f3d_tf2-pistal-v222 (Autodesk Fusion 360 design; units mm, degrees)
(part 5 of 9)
sketch "Sketch81" plane through (0, 157.95, 0) normal (0, 1, 0) x axis (-1, 0, 0)
  line L1 (-8.4524, 10) -> (-5.806, 10)
  line L2 (-8.4524, 5.25) -> (-8.4524, 10)
  line L3 (-8.4524, 1) -> (-8.4524, 5.25)
  line L4 (8.4524, 1) -> (-8.4524, 1)
  line L5 (8.4524, 10) -> (8.4524, 1)
  line L6 (5.8059, 10) -> (8.4524, 10)
  line L7 (-8.4524, 13.0239) -> (-6.8669, 13.0239)
  line L8 (-8.4524, 10) -> (-5.806, 10)
  line L9 (-8.4524, 10) -> (-8.4524, 13.0239)
  arc A1 centre (0, 13.7351) radius 6.9036 clockwise from (5.8059, 10) to (-5.806, 10)
  arc A2 centre (0, 13.7351) radius 6.9036 clockwise from (5.8059, 10) to (-5.806, 10)
  arc A3 centre (0, 13.7351) radius 6.9036 clockwise from (-6.8669, 13.0239) to (6.8668, 13.0239)
  circle C1 centre (0, 13.7351) radius 6.9036
  point P10 (-5.806, 10)
  point P14 (-8.4524, 13.0239)
  point P19 (-8.4524, 13.0239)
  point P17 (-8.4524, 10)
  point P20 (-8.4524, 10)
  concentric A1 C1
  coincident P10 C1
  coincident P14 P19
  coincident P17 P20
extrude "Extrude77" new body sketch "Sketch81" profile of L1 L7 L8 C1 L9 against normal blind 2.1
mirror "Mirror24" mirrorStitchTolerance 0.1
combine "Combine75"
delete_face "DeleteFace79"
combine "Combine76" bodies "Barrel"
delete_face "DeleteFace80"
move_face "MoveFace115" TranslateX -0.232 TranslateY 0 TranslateZ 0
extrude "Extrude78" add of existing geometry blind 0
move_face "MoveFace116" TranslateX 0 TranslateY 0 TranslateZ 0
split "Split28" bodies "Trigger Pannel_R (1)"
remove_body "RemoveBody37"
move_face "MoveFace117" TranslateX 3 TranslateY 0 TranslateZ 0
split "Split29" bodies "Trigger Pannel_R (1)"
remove_body "RemoveBody38"
split "Split30" bodies "Trigger Pannel_L (1)"
remove_body "RemoveBody39"
move_face "MoveFace118" TranslateX -3 TranslateY 0 TranslateZ 0
split "Split31" bodies "Trigger Pannel_L (1)"
remove_body "RemoveBody40"
sketch "Sketch82" plane through (-0.0003, 0, 0) normal (-1, 0, 0) x axis (0, -1, 0)
  line L1 (-144.2618, -68.8977) -> (-159.3646, -64.9915)
  curve K1 (-143.2922, -67.2348) -> (-144.2618, -68.8977)
  curve K2 (-143.2922, -67.2348) -> (-146.2926, -63.0126)
  curve K3 (-146.2926, -63.0126) -> (-146.4498, -62.6853)
  curve K4 (-147.5496, -59.6077) -> (-148.3256, -54.5282)
  curve K5 (-146.4498, -62.6853) -> (-147.5496, -59.6077)
  curve K6 (-146.2926, -63.0126) -> (-146.4498, -62.6853)
  curve K7 (-134.7944, -30.1716) -> (-146.2926, -63.0126)
  curve K8 (-135.347, -29.366) -> (-134.7944, -30.1716)
  curve K9 (-136.1286, -29.6952) -> (-135.347, -29.366)
  line L2 (-136.7565, -29.9764) -> (-136.1286, -29.6952)
  line L3 (-136.8552, -29.6952) -> (-136.7565, -29.9764)
  line L4 (-144.3129, -29.6952) -> (-136.8552, -29.6952)
  line L5 (-159.3646, -64.9915) -> (-144.3129, -29.6952)
  line L6 (-145.5, -62.5) -> (-146.8762, -63.1863)
  line L7 (-147.4329, -53.781) -> (-145.5, -62.5)
  line L8 (-150, -53.781) -> (-147.4329, -53.781)
  line L9 (-146.8762, -63.1863) -> (-150, -53.781)
  horizontal L8
extrude "Extrude79" new body sketch "Sketch82" profile of L6 L7 L8 L9 against normal blind 8
move_face "MoveFace119" TranslateX 0 TranslateY 0 TranslateZ -0.3
fillet "Fillet95" radius 4
fillet "Fillet96" radius 1.5
mirror "Mirror25" mirrorStitchTolerance 0.1
combine "Combine77"
combine "Combine78"
move_face "MoveFace120" TranslateX 0 TranslateY 0 TranslateZ 0
move_face "MoveFace121" TranslateX 5 TranslateY 0 TranslateZ 0
split "Split32" bodies "GripAft_R (1)"
remove_body "RemoveBody41"
move_face "MoveFace122" TranslateX -5 TranslateY 0 TranslateZ 0
split "Split33" bodies "GripAft_L (1)"
remove_body "RemoveBody42"
sketch "Sketch83" plane through (-8.7048, 0, 0) normal (-1, 0, 0) x axis (0, -1, 0)
  line L1 (-245.977, -21.5753) -> (-249.4899, -14.9957)
  line L2 (-220.43, -21.5753) -> (-245.977, -21.5753)
  line L3 (-219.864, -18.4055) -> (-220.43, -21.5753)
  line L4 (-214.6554, -27.0757) -> (-215.9162, -18.4672)
  line L5 (-219.3284, -44.1367) -> (-214.6554, -27.0757)
  line L6 (-216.9388, -45.4009) -> (-218.364, -45.4009)
  line L7 (-215.7169, -43.7389) -> (-215.9754, -44.6687)
  line L8 (-216.8579, -41.6824) -> (-215.9084, -42.8355)
  line L9 (-208.8666, -10.9038) -> (-217.0504, -40.7825)
  line L10 (-248.3191, -10.9038) -> (-208.8666, -10.9038)
  line L11 (-249.4926, -13.1167) -> (-248.3191, -10.9038)
  line L12 (-213.391, -27.422) -> (-214.6554, -27.0757)
  line L13 (-216.667, -39.3825) -> (-217.9314, -39.0362)
  circle C1 centre (-239.5412, -17) radius 2.25
  arc A1 centre (-247.7257, -14.0537) radius 2 clockwise from (-249.4899, -14.9957) to (-249.4926, -13.1167)
  arc A2 centre (-217.8951, -18.7571) radius 2 clockwise from (-219.864, -18.4055) to (-215.9162, -18.4672)
  arc A3 centre (-218.364, -44.4009) radius 1 clockwise from (-218.364, -45.4009) to (-219.3284, -44.1367)
  arc A4 centre (-216.9388, -44.4009) radius 1 clockwise from (-215.9754, -44.6687) to (-216.9388, -45.4009)
  arc A5 centre (-216.6804, -43.4711) radius 1 clockwise from (-215.9084, -42.8355) to (-215.7169, -43.7389)
  arc A6 centre (-216.086, -41.0467) radius 1 clockwise from (-216.8579, -41.6824) to (-217.0504, -40.7825)
  point P11 (-214.6554, -27.0757)
  point P26 (-214.6554, -27.0757)
  point P27 (-213.391, -27.422)
  point P28 (-217.9314, -39.0362)
  point P29 (-216.667, -39.3825)
  coincident P11 P26
  coincident L9 P27
  perpendicular L9 L12
  coincident L5 P28
  coincident L9 P29
  perpendicular L9 L13
extrude "Extrude80" cut sketch "Sketch83" profile of L5 L9 L12 L13 against normal blind 17.5
move "Move60"
combine "Combine79"
move "Move61"
delete_face "DeleteFace81"
sketch "Sketch84" plane through (-8.7048, 0, 0) normal (-1, 0, 0) x axis (0, -1, 0)
  line L1 (-219.9351, -24.4038) -> (-243.4668, -24.4038)
  line L2 (-218.864, -18.4055) -> (-219.9351, -24.4038)
  line L3 (-213.6554, -27.0757) -> (-214.9162, -18.4672)
  line L4 (-214.63, -30.634) -> (-213.6554, -27.0757)
  line L5 (-212.2404, -31.8982) -> (-213.6656, -31.8982)
  line L6 (-211.0185, -30.2363) -> (-211.277, -31.166)
  line L7 (-212.1595, -28.1797) -> (-211.21, -29.3328)
  line L8 (-207.8666, -10.9038) -> (-212.352, -27.2799)
  line L9 (-247.3191, -10.9038) -> (-207.8666, -10.9038)
  line L10 (-248.4926, -13.1167) -> (-247.3191, -10.9038)
  line L11 (-243.4668, -24.4038) -> (-248.4899, -14.9957)
  line L12 (-214.0467, -24.4038) -> (-219.9351, -24.4038)
  line L13 (-214.663, -24.4038) -> (-214.663, -30.9696)
  arc A1 centre (-216.8951, -18.7571) radius 2 clockwise from (-218.864, -18.4055) to (-214.9162, -18.4672)
  arc A2 centre (-213.6656, -30.8982) radius 1 clockwise from (-213.6656, -31.8982) to (-214.63, -30.634)
  arc A3 centre (-212.2404, -30.8982) radius 1 clockwise from (-211.277, -31.166) to (-212.2404, -31.8982)
  arc A4 centre (-211.982, -29.9685) radius 1 clockwise from (-211.21, -29.3328) to (-211.0185, -30.2363)
  arc A5 centre (-211.3876, -27.5441) radius 1 clockwise from (-212.1595, -28.1797) to (-212.352, -27.2799)
  arc A6 centre (-246.7257, -14.0537) radius 2 clockwise from (-248.4899, -14.9957) to (-248.4926, -13.1167)
  circle C1 centre (-238.5412, -17) radius 2.25
  point P3 (-219.9351, -24.4038)
  point P26 (-219.9351, -24.4038)
  point P27 (-214.0467, -24.4038)
  point P28 (-214.663, -30.9696)
  point P29 (-214.663, -24.4038)
  coincident P3 P26
  coincident L3 P27
  parallel L1 L12
  coincident A2 P28
  coincident L12 P29
  perpendicular L12 L13
extrude "Extrude81" add sketch "Sketch84" profile of L2 A1 L3 L4 A2 L12 L13 against normal blind 17.5
delete_face "DeleteFace82"
move_face "MoveFace123" RotateAngle 20
move_face "MoveFace124"
move_face "MoveFace125"
delete_face "DeleteFace83"
sketch "Sketch85" plane through (8.7952, 0, 0) normal (1, 0, 0) x axis (0, 1, 0)
  line L1 (207.8666, -10.9038) -> (259.5128, -10.9038)
  line L2 (212.352, -27.2799) -> (207.8666, -10.9038)
  line L3 (211.21, -29.3328) -> (212.1595, -28.1797)
  line L4 (211.277, -31.166) -> (211.0185, -30.2363)
  line L5 (213.6656, -31.8982) -> (212.2404, -31.8982)
  line L6 (214.663, -25.4038) -> (214.663, -30.8269)
  line L7 (243.3532, -25.4038) -> (214.663, -25.4038)
  line L8 (259.5128, -10.9038) -> (243.3532, -25.4038)
  line L9 (233.7413, 10) -> (252.4034, -14.8943)
  line L10 (252.4034, -14.8943) -> (252.4034, -16.3824)
  line L11 (252.8977, -18.1538) -> (251.7434, -17.8671)
  arc A1 centre (211.3876, -27.5441) radius 1 clockwise from (212.352, -27.2799) to (212.1595, -28.1797)
  arc A2 centre (211.982, -29.9685) radius 1 clockwise from (211.0185, -30.2363) to (211.21, -29.3328)
  arc A3 centre (212.2404, -30.8982) radius 1 clockwise from (212.2404, -31.8982) to (211.277, -31.166)
  arc A4 centre (213.6656, -30.8982) radius 1 clockwise from (214.663, -30.8269) to (213.6656, -31.8982)
  arc A5 centre (250.4034, -16.3824) radius 2 clockwise from (252.4034, -16.3824) to (251.7434, -17.8671)
  point P21 (251.7434, -17.8671)
  point P23 (251.7434, -17.8671)
  coincident P21 P23
extrude "Extrude82" cut sketch "Sketch85" profile of L1 L8 L9 L10 A5 L11 against normal blind 17.5
sketch "Sketch86" plane through (-8.7048, 0, 0) normal (-1, 0, 0) x axis (0, -1, 0)
  line L1 (-251.7505, -17.8688) -> (-251.7434, -17.8671)
  line L2 (-243.3532, -25.4038) -> (-251.7505, -17.8688)
  line L3 (-214.663, -25.4038) -> (-243.3532, -25.4038)
  line L4 (-214.663, -30.8269) -> (-214.663, -25.4038)
  line L5 (-212.2404, -31.8982) -> (-213.6656, -31.8982)
  line L6 (-211.0185, -30.2363) -> (-211.277, -31.166)
  line L7 (-212.1595, -28.1797) -> (-211.21, -29.3328)
  line L8 (-207.8666, -10.9038) -> (-212.352, -27.2799)
  line L9 (-249.4118, -10.9038) -> (-207.8666, -10.9038)
  line L10 (-252.4034, -14.8943) -> (-249.4118, -10.9038)
  line L11 (-252.4034, -16.3824) -> (-252.4034, -14.8943)
  arc A1 centre (-213.6656, -30.8982) radius 1 clockwise from (-213.6656, -31.8982) to (-214.663, -30.8269)
  arc A2 centre (-212.2404, -30.8982) radius 1 clockwise from (-211.277, -31.166) to (-212.2404, -31.8982)
  arc A3 centre (-211.982, -29.9685) radius 1 clockwise from (-211.21, -29.3328) to (-211.0185, -30.2363)
  arc A4 centre (-211.3876, -27.5441) radius 1 clockwise from (-212.1595, -28.1797) to (-212.352, -27.2799)
  arc A5 centre (-250.4034, -16.3824) radius 2 clockwise from (-251.7434, -17.8671) to (-252.4034, -16.3824)
  circle C1 centre (-234, -15) radius 2
  dimension "d704" diameter C1 = 4
extrude "Extrude83" cut sketch "Sketch86" profile of C1 against normal blind 35 and along normal blind 42
delete_face "DeleteFace84"
move_face "MoveFace126"
move_face "MoveFace127"
move_face "MoveFace128"
fillet "Fillet97" radius 5
move_face "MoveFace129"
fillet "Fillet98" radius 10
fillet "Fillet99" radius 4
sketch "Sketch87" plane through (8.7952, 0, 0) normal (1, 0, 0) x axis (0, 1, 0)
  line L1 (212.352, -27.2799) -> (211.3292, -23.5455)
  line L2 (211.21, -29.3328) -> (212.1595, -28.1797)
  line L3 (211.277, -31.166) -> (211.0185, -30.2363)
  line L4 (213.5959, -31.8982) -> (212.2404, -31.8982)
  line L5 (218.1133, -24.439) -> (218.4255, -25.6041)
  line L6 (250.0399, -19.4038) -> (221.9771, -19.4038)
  line L7 (251.7505, -17.8688) -> (250.0399, -19.4038)
  line L8 (251.7434, -17.8671) -> (251.7505, -17.8688)
  line L9 (252.4034, -14.8943) -> (252.4034, -16.3824)
  line L10 (249.4118, -10.9038) -> (252.4034, -14.8943)
  line L11 (220.9739, -10.9038) -> (249.4118, -10.9038)
  line L12 (240.3316, -19.4038) -> (240.3316, -10.9038)
  arc A1 centre (220.9739, -20.9038) radius 10 clockwise from (211.3292, -23.5455) to (220.9739, -10.9038)
  arc A2 centre (211.3876, -27.5441) radius 1 clockwise from (212.352, -27.2799) to (212.1595, -28.1797)
  arc A3 centre (211.982, -29.9685) radius 1 clockwise from (211.0185, -30.2363) to (211.21, -29.3328)
  arc A4 centre (212.2404, -30.8982) radius 1 clockwise from (212.2404, -31.8982) to (211.277, -31.166)
  arc A5 centre (213.5959, -26.8982) radius 5 clockwise from (218.4255, -25.6041) to (213.5959, -31.8982)
  arc A6 centre (221.9771, -23.4038) radius 4 clockwise from (218.1133, -24.439) to (221.9771, -19.4038)
  arc A7 centre (250.4034, -16.3824) radius 2 clockwise from (252.4034, -16.3824) to (251.7434, -17.8671)
  circle C1 centre (234, -15) radius 2
  point P28 (240.3316, -10.9038)
  point P29 (240.3316, -19.4038)
  coincident L11 P28
  coincident L6 P29
  perpendicular L6 L12
extrude "Extrude84" new body sketch "Sketch87" profile of L6 L7 L8 A7 L9 L10 L11 L12 along normal blind 11.202
extrude "Extrude85" add of existing geometry blind 5
sketch "Sketch88" plane through (0, 240.3316, 0) normal (0, -1, 0) x axis (1, 0, 0)
  line L1 (8.7952, -19.4038) -> (8.7952, -10.9038)
  line L2 (24.9972, -19.4038) -> (8.7952, -19.4038)
  line L3 (24.9972, -10.9038) -> (24.9972, -19.4038)
  line L4 (8.7952, -10.9038) -> (24.9972, -10.9038)
  line L5 (19.9977, -29.2452) -> (19.9977, 10)
  line L6 (19.9977, -72.0555) -> (19.9977, -29.2452)
  line L7 (19.9977, -72.7728) -> (19.9977, -72.0555)
  line L8 (19.9977, -84.669) -> (19.9977, -72.7728)
  line L9 (19.9977, -60.3717) -> (19.9977, -84.669)
  line L10 (19.9977, -48.7291) -> (19.9977, -60.3717)
  line L11 (19.9977, 10) -> (19.9977, -48.7291)
extrude "Extrude86" new body sketch "Sketch88" profile of L2 L3 L4 L5 L11 along normal blind 55
sketch "Sketch89" plane through (0, 0, -10.9038) normal (0, 0, 1) x axis (-1, 0, 0)
  line L1 (-19.9977, -240.3316) -> (-24.9972, -240.3316)
  line L2 (-19.9977, -185.3316) -> (-19.9977, -240.3316)
  line L3 (-24.9972, -185.3316) -> (-19.9977, -185.3316)
  line L4 (-24.9972, -240.3316) -> (-24.9972, -185.3316)
  line L5 (-19.9977, -185.3316) -> (-19.9977, -240.3316)
  line L6 (-24.9972, -240.3316) -> (-8.7952, -240.3316)
  line L7 (-18.6852, -232) -> (-17.8895, -236)
  line L8 (-19.9973, -225.4034) -> (-18.3388, -233.7413)
  line L9 (-17.3185, -238.8709) -> (-19.9973, -225.4034)
  line L10 (-17.3185, -238.8709) -> (-17.3185, -238.8705)
  line L11 (-18.3388, -233.7413) -> (-17.3185, -238.8705)
  line L12 (-17.8193, -240.3316) -> (-19.9977, -229.3801)
  point P16 (-19.9977, -229.3801)
  point P17 (-17.8193, -240.3316)
  coincident L5 P16
  coincident L6 P17
  parallel L8 L12
extrude "Extrude87" add sketch "Sketch89" profile of L2 L5 L6 L12 against normal blind 8.5
sketch "Sketch90" plane through (0, 0, -10.9038) normal (0, 0, 1) x axis (-1, 0, 0)
  line L1 (-8.7952, -240.3316) -> (-8.7952, -249.4118)
  line L2 (-17.8193, -240.3316) -> (-8.7952, -240.3316)
  line L3 (-19.9977, -229.3801) -> (-17.8193, -240.3316)
  line L4 (-19.9977, -185.3316) -> (-19.9977, -229.3801)
  line L5 (-24.9972, -185.3316) -> (-19.9977, -185.3316)
  line L6 (-24.9972, -249.4118) -> (-24.9972, -185.3316)
  line L7 (-8.7952, -249.4118) -> (-24.9972, -249.4118)
  line L8 (-26.8101, -222.3485) -> (-20.3027, -255.0631)
  line L9 (-17.8193, -240.3316) -> (-19.9977, -229.3801)
  line L10 (-28.2479, -253.9675) -> (-20.3027, -255.0631)
  line L11 (-27.0093, -221.3469) -> (-28.2479, -253.9675)
  line L12 (-26.8101, -222.3485) -> (-27.0093, -221.3469)
  parallel L8 L9
  parallel L8 L12
extrude "Extrude88" cut sketch "Sketch90" profile of L6 L7 L8 L10 L11 L12 against normal blind 20
fillet "Fillet100" radius 490
sketch "Sketch91" plane through (21.9977, 0, 0) normal (1, 0, 0) x axis (0, 1, 0)
  line L1 (197.128, -152.3541) -> (197.128, -141.3784)
  line L2 (198.032, -155.4234) -> (197.128, -152.3541)
  line L3 (251.5442, -141.4509) -> (202.4935, -157.7558)
  line L4 (220.8838, -56.1363) -> (253.6825, -136.8114)
  line L5 (220.8838, -21.4864) -> (220.8838, -56.1363)
  line L6 (162.8556, -15.4864) -> (214.8838, -15.4864)
  line L7 (197.128, -141.3784) -> (157.1727, -23.4112)
  curve K1 (232, -15) -> (232, -15)
  curve K2 (232, -15) -> (232, -15)
  line L8 (260, -25.7905) -> (184.5949, -25.7905)
  line L9 (181.1045, -9.8094) -> (184.5949, -25.7905)
  line L10 (258.469, -9.8094) -> (181.1045, -9.8094)
  line L11 (260, -25.7905) -> (258.469, -9.8094)
  arc A1 centre (201.3894, -154.4345) radius 3.5 clockwise from (202.4935, -157.7558) to (198.032, -155.4234)
  arc A2 centre (250.4402, -138.1296) radius 3.5 clockwise from (253.6825, -136.8114) to (251.5442, -141.4509)
  arc A3 centre (214.8838, -21.4864) radius 6 clockwise from (214.8838, -15.4864) to (220.8838, -21.4864)
  arc A4 centre (162.8556, -21.4864) radius 6 clockwise from (157.1727, -23.4112) to (162.8556, -15.4864)
  circle C1 centre (210.9636, -95.9994) radius 18.6716
  circle C2 centre (234, -15) radius 2
  parallel L6 L8
  horizontal L10
split "Split34" bodies "Grip plate_L"
remove_body "RemoveBody43"
remove_body "RemoveBody44"
fillet "Fillet101" radius 5
fillet "Fillet102" radius 0.9
fillet "Fillet103" radius 0.9
move_face "MoveFace130"
fillet "Fillet104" radius 4
sketch "Sketch92" plane through (24.9972, 0, 0) normal (1, 0, 0) x axis (0, 1, 0)
  line L1 (185.3316, -15.4038) -> (185.3316, -14.9038)
  line L2 (231.4625, -10.9038) -> (231.4625, -19.4038)
  line L3 (189.3316, -10.9038) -> (226.8664, -10.9038)
  line L4 (226.8664, -19.4038) -> (189.3316, -19.4038)
  line L5 (240.3316, -19.4038) -> (240.3316, -10.9038)
  line L6 (250.0399, -19.4038) -> (249.4118, -10.9038)
  line L7 (249.4118, -10.9038) -> (240.3316, -10.9038)
  line L8 (250.0399, -19.4038) -> (240.3316, -19.4038)
  arc A1 centre (189.3316, -14.9038) radius 4 clockwise from (185.3316, -14.9038) to (189.3316, -10.9038)
  arc A2 centre (189.3316, -15.4038) radius 4 clockwise from (189.3316, -19.4038) to (185.3316, -15.4038)
  perpendicular L5 L7
  perpendicular L5 L8
split "Split35" bodies "GripAft_L"
remove_body "RemoveBody45"
remove_body "RemoveBody46"
extrude "Extrude89" cut of existing geometry blind -21
extrude "Extrude90" cut of existing geometry blind -12
move_face "MoveFace131"
extrude "Extrude91" cut of existing geometry blind -3 bodies "GripAft_R (1)"
remove_body "RemoveBody47"
remove_body "RemoveBody48"
move_face "MoveFace132"
move "Move62" RotateAngle 5
move_face "MoveFace133" TranslateX 0 TranslateY 0 TranslateZ -1.5
move_face "MoveFace134" TranslateX 0 TranslateY 0 TranslateZ 1.592
move_face "MoveFace135" TranslateX 0 TranslateY 0 TranslateZ 5
move_face "MoveFace136" TranslateX 0 TranslateY 0 TranslateZ 1.5
fillet "Fillet105" radius 4.5
fillet "Fillet106" radius 3.5
fillet "Fillet107" radius 3.5
fillet "Fillet108" radius 3.5
move "Move63" RotateAngle -5
fillet "Fillet109" radius 1.5
sketch "Sketch93" plane through (24.9972, 0, 0) normal (1, 0, 0) x axis (0, 1, 0)
  line L1 (185.3316, -15.4038) -> (185.3316, -14.9038)
  line L2 (231.4625, -19.4038) -> (189.3316, -19.4038)
  line L3 (231.4625, -10.9038) -> (231.4625, -19.4038)
  line L4 (189.3316, -10.9038) -> (231.4625, -10.9038)
  line L5 (207, -15.4038) -> (189.3316, -15.4038)
  line L6 (207, -14.9038) -> (189.3316, -14.9038)
  line L7 (211, -14.9038) -> (211, -15.4038)
  line L8 (210.8021, -13.6611) -> (185.5296, -13.6611)
  line L9 (210.8021, -16.6464) -> (185.5296, -16.6464)
  arc A1 centre (189.3316, -14.9038) radius 4 clockwise from (185.3316, -14.9038) to (189.3316, -10.9038)
  arc A2 centre (189.3316, -15.4038) radius 4 clockwise from (189.3316, -19.4038) to (185.3316, -15.4038)
  arc A3 centre (207, -14.9038) radius 4 clockwise from (207, -10.9038) to (211, -14.9038)
  arc A4 centre (207, -15.4038) radius 4 clockwise from (211, -15.4038) to (207, -19.4038)
  point P7 (189.3316, -15.4038)
  point P10 (189.3316, -15.4038)
  point P4 (189.3316, -14.9038)
  point P12 (189.3316, -14.9038)
  point P16 (207, -10.9038)
  point P13 (207, -14.9038)
  point P14 (207, -14.9038)
  point P18 (207, -19.4038)
  point P11 (207, -15.4038)
  point P17 (207, -15.4038)
  point P20 (185.5296, -13.6611)
  point P21 (210.8021, -13.6611)
  point P22 (185.5296, -16.6464)
  point P23 (210.8021, -16.6464)
  coincident P7 P10
  parallel L4 L5
  coincident P4 P12
  parallel L5 L6
  coincident L4 P16
  coincident P13 P14
  coincident L2 P18
  coincident P11 P17
  tangent A3 L7
  coincident A1 P20
  coincident A3 P21
  perpendicular L7 L8
  coincident A2 P22
  coincident A4 P23
  parallel L5 L9
extrude "Extrude92" add sketch "Sketch93" profile of A1 L1 A2 A3 A4 L7 L8 L9 along normal blind 4
fillet "Fillet110" radius 3
fillet "Fillet111" radius 1.5
fillet "Fillet112" radius 1
fillet "Fillet113" radius 1
fillet "Fillet114" radius 2.5
fillet "Fillet115" radius 0.5
mirror "Mirror26" mirrorStitchTolerance 0.1
move "Move64"
move "Move65" TranslateX 0.001 TranslateY 0 TranslateZ 0
combine "Combine80"
sketch "Sketch94" plane through (24.9972, 0, 0) normal (1, 0, 0) x axis (0, 1, 0)
  line L1 (189.3316, -11.9038) -> (223.6753, -11.9038)
  line L2 (209.5001, -12.6611) -> (187.339, -12.6611)
  line L3 (187.339, -17.6464) -> (209.5, -17.6464)
  line L4 (223.6753, -18.4038) -> (189.3316, -18.4038)
  line L5 (231.2163, -13.1111) -> (231.2163, -17.1964)
  curve K1 (232, -15) -> (232, -15)
  closed curve K2 centre (223.6753, -13.4038)
  arc A1 centre (189.3316, -14.9038) radius 3 clockwise from (187.339, -12.6611) to (189.3316, -11.9038)
  arc A2 centre (209.5001, -15.1611) radius 2.5 clockwise from (209.5001, -12.6611) to (212, -15.1415)
  arc A3 centre (209.5, -15.1464) radius 2.5 clockwise from (212, -15.1415) to (209.5, -17.6464)
  arc A4 centre (189.3316, -15.4038) radius 3 clockwise from (189.3316, -18.4038) to (187.339, -17.6464)
  closed curve K3 centre (223.6753, -16.9038)
  circle C1 centre (234, -15) radius 2
extrude "Extrude93" cut sketch "Sketch94" profile of K1 against normal blind 60
fillet "Fillet116" radius 0.5
sketch "Sketch95" plane through (13, 0, 0) normal (-1, 0, 0) x axis (0, -1, 0)
  line L1 (-227, 10) -> (-157.3502, 10)
  line L2 (-227, -6) -> (-227, 10)
  line L3 (-162.4167, -6) -> (-227, -6)
  line L4 (-157.3502, 10) -> (-162.4167, -6)
  circle C1 centre (-185.5, -18.5) radius 41.6604
extrude "Extrude94" new body sketch "Sketch95" profile of L1 L2 L3 C1 along normal blind 3.995
mirror "Mirror27" mirrorStitchTolerance 0.1
combine "Combine81"
combine "Combine82"
move_face "MoveFace137"
sketch "Sketch96" plane through (-9.005, 0, 0) normal (1, 0, 0) x axis (0, 1, 0)
  line L1 (227, 10) -> (227, -14.8472)
  line L2 (215.8866, 10) -> (227, 10)
  curve K1 (252.6258, 16.3802) -> (227, 10)
  line L3 (252.6258, 12.1174) -> (252.6258, 16.3802)
  curve K2 (244.6123, 12.1174) -> (252.6258, 12.1174)
  curve K3 (239, 8) -> (244.6123, 12.1174)
  line L4 (241.0777, 2.8538) -> (224.9079, 0.1947)
  curve K4 (237.1263, 2.204) -> (239, 8)
  curve K5 (228.6359, 0.8078) -> (227, 10)
  arc A1 centre (185.5, -18.5) radius 41.6604 clockwise from (215.8866, 10) to (227, -14.8472)
  circle C1 centre (230, 6) radius 2.6797
  point P5 (227, 10)
  point P6 (227, 10)
  point P17 (237.1263, 2.204)
  point P18 (227, 10)
  point P21 (228.6359, 0.8078)
  coincident P5 P6
  vertical L3
  coincident L4 P17
  coincident P6 P18
  coincident L4 P21
extrude "Extrude95" new body sketch "Sketch96" profile of L1 K1 L3 K2 K3 C1 L4 K4 K5 blind 16.01 from offset 1
sketch "Sketch97" plane through (-9.0048, 0, 0) normal (1, 0, 0) x axis (0, 1, 0)
  line L1 (233.7413, 10) -> (246.4884, -7.004)
  line L2 (227, 10) -> (233.7413, 10)
  line L3 (227, -25.812) -> (227, 10)
  line L4 (228.8407, -19.312) -> (227, -25.812)
  line L5 (250.1425, -19.312) -> (228.8407, -19.312)
  line L6 (250.1428, -19.3118) -> (250.1425, -19.312)
  line L7 (241.8316, -19.3118) -> (250.1428, -19.3118)
  line L8 (237.3316, -13.9038) -> (237.3316, -14.8118)
  line L9 (245.2882, -9.4038) -> (241.8316, -9.4038)
  line L10 (242.4574, -1.627) -> (238.6497, -10.7218)
  arc A1 centre (245.2882, -7.9038) radius 1.5 clockwise from (246.4884, -7.004) to (245.2882, -9.4038)
  arc A2 centre (241.8316, -14.8118) radius 4.5 clockwise from (241.8316, -19.3118) to (237.3316, -14.8118)
  arc A3 centre (241.8316, -13.9038) radius 4.5 clockwise from (237.3316, -13.9038) to (241.8316, -9.4038)
  circle C1 centre (234, -15) radius 2
  point P18 (238.6497, -10.7218)
  point P19 (242.4574, -1.627)
  midpoint A3 P18
  coincident L1 P19
extrude "Extrude96" new body sketch "Sketch97" profile of A1 L1 A3 L9 L10 along normal blind 18
fillet "Fillet117" radius 1
split "Split36"
combine "Combine83"
combine "Combine84" bodies "GripAft_L  (1)"
move_face "MoveFace138"
fillet "Fillet118" radius 1
combine "Combine85" bodies "GripAft_L  (1)"
delete_face "DeleteFace85"
delete_face "DeleteFace86"
delete_face "DeleteFace87"
delete_face "DeleteFace88"
split "Split37" bodies "Mag Release_L"
sketch "Sketch98" plane through (0, 0, 0) normal (1, 0, 0) x axis (0, 1, 0)
  line L1 (251.7434, -17.8671) -> (251.7505, -17.8688)
  line L2 (252.4034, -14.8943) -> (252.4034, -16.3824)
  line L3 (250.4618, -12.3044) -> (252.4034, -14.8943)
  line L4 (220.9739, -10.9038) -> (247.6613, -10.9038)
  line L5 (212.352, -27.2799) -> (211.3292, -23.5455)
  line L6 (211.21, -29.3328) -> (212.1595, -28.1797)
  line L7 (211.277, -31.166) -> (211.0185, -30.2363)
  line L8 (213.5959, -31.8982) -> (212.2404, -31.8982)
  line L9 (218.1133, -24.439) -> (218.4255, -25.6041)
  line L10 (248.6998, -19.4038) -> (221.9771, -19.4038)
  line L11 (251.7505, -17.8688) -> (251.0373, -18.5088)
  line L12 (243, -17) -> (247, -17)
  line L13 (243, -13) -> (243, -17)
  line L14 (247, -13) -> (243, -13)
  line L15 (247, -17) -> (247, -13)
  line L16 (243, -13) -> (247, -17)
  line L17 (247, -13) -> (243, -17)
  circle C1 centre (234, -15) radius 2
  arc A1 centre (250.4034, -16.3824) radius 2 clockwise from (252.4034, -16.3824) to (251.7434, -17.8671)
  arc A2 centre (247.6613, -14.4038) radius 3.5 clockwise from (247.6613, -10.9038) to (250.4618, -12.3044)
  arc A3 centre (220.9739, -20.9038) radius 10 clockwise from (211.3292, -23.5455) to (220.9739, -10.9038)
  arc A4 centre (211.3876, -27.5441) radius 1 clockwise from (212.352, -27.2799) to (212.1595, -28.1797)
  arc A5 centre (211.982, -29.9685) radius 1 clockwise from (211.0185, -30.2363) to (211.21, -29.3328)
  arc A6 centre (212.2404, -30.8982) radius 1 clockwise from (212.2404, -31.8982) to (211.277, -31.166)
  arc A7 centre (213.5959, -26.8982) radius 5 clockwise from (218.4255, -25.6041) to (213.5959, -31.8982)
  arc A8 centre (221.9771, -23.4038) radius 4 clockwise from (218.1133, -24.439) to (221.9771, -19.4038)
  arc A9 centre (248.6998, -15.9038) radius 3.5 clockwise from (251.0373, -18.5088) to (248.6998, -19.4038)
  point P36 (245, -15)
  horizontal L12
  perpendicular L12 L13
  parallel L12 L14
  parallel L13 L15
  coincident L16 P36
  coincident L17 P36
extrude "Extrude97" add sketch "Sketch98" profile of L12 L13 L14 L15 along normal blind 3
combine "Combine86"
move_face "MoveFace139"
move_face "MoveFace140"
move_face "MoveFace141"
move_face "MoveFace142"
chamfer "Chamfer27" distance 0.2
move_face "MoveFace143"
combine "Combine87"
remove_body "RemoveBody49"
chamfer "Chamfer28" distance 4
chamfer "Chamfer29" distance 5.65
chamfer "Chamfer30" distance 10.43
move_face "MoveFace144"
chamfer "Chamfer31" distance 5.7725
chamfer "Chamfer32" distance 20.4
delete_face "DeleteFace89"
delete_face "DeleteFace90"
delete_face "DeleteFace91"
move_face "MoveFace145"
move_face "MoveFace146"
move_face "MoveFace147"
chamfer "Chamfer33" distance 20
extrude "Extrude98" cut of existing geometry blind -0.2
remove_body "RemoveBody50"
move_face "MoveFace148"
extrude "Extrude99" cut of existing geometry blind -5
fillet "Fillet119" radius 18
sketch "Sketch99" plane through (0, 19.0955, 0) normal (0, -1, 0) x axis (1, 0, 0)
  line L1 (-1.9973, 30) -> (1.9977, 30)
  line L2 (-17.9973, -3.324) -> (-17.9973, 20.2462)
  line L3 (17.9977, -3.324) -> (-17.9973, -3.324)
  line L4 (17.9977, 20.2462) -> (17.9977, -3.324)
  arc A1 centre (1.9977, 12) radius 18 clockwise from (1.9977, 30) to (17.9977, 20.2462)
  arc A2 centre (-1.9973, 12) radius 18 clockwise from (-17.9973, 20.2462) to (-1.9973, 30)
  circle C1 centre (0, 13.7351) radius 10.8905
  circle C2 centre (0, 13.7351) radius 10.8905
  circle C3 centre (0, 13.7351) radius 13.7351
  point P1 (0, 0)
  concentric C1 C2
  concentric C1 C3
  coincident P1 C3
extrude "Extrude100" add sketch "Sketch99" profile of C1 C2 C3 along normal blind 5
sketch "Sketch100" plane through (0, 19.0955, 0) normal (0, -1, 0) x axis (1, 0, 0)
  line L1 (-1.9973, 30) -> (1.9977, 30)
  line L2 (-17.9973, -3.324) -> (-17.9973, 20.2462)
  line L3 (17.9977, -3.324) -> (-17.9973, -3.324)
  line L4 (17.9977, 20.2462) -> (17.9977, -3.324)
  line L5 (-19.9973, 12) -> (-19.9973, -2.8221)
  line L6 (19.9977, 12) -> (19.9977, -2.8221)
  line L7 (1.9977, 30) -> (-1.9973, 30)
  line L8 (-20.2973, -3) -> (-20.2973, 12)
  line L9 (20.2977, -2.8221) -> (20.2977, 12)
  line L10 (1.9977, 30.3) -> (-1.9973, 30.3)
  line L11 (1.9977, 32.3224) -> (-1.9973, 32.3224)
  line L12 (-22.3197, -3) -> (-22.3197, 12)
  line L13 (-20.2973, -3) -> (-22.3197, -3)
  line L14 (22.32, -2.8221) -> (22.32, 12)
  line L15 (20.2977, -2.8221) -> (22.32, -2.8221)
  circle C1 centre (0, 13.7351) radius 13.7351
  arc A1 centre (1.9977, 12) radius 18 clockwise from (1.9977, 30) to (17.9977, 20.2462)
  arc A2 centre (-1.9973, 12) radius 18 clockwise from (-17.9973, 20.2462) to (-1.9973, 30)
  arc A3 centre (1.9977, 12) radius 18 clockwise from (17.9977, 20.2462) to (19.9977, 12)
  arc A4 centre (-1.9973, 12) radius 18 clockwise from (-19.9973, 12) to (-17.9973, 20.2462)
  arc A5 centre (-1.9973, 12) radius 18 clockwise from (-17.9973, 20.2462) to (-1.9973, 30)
  arc A6 centre (1.9977, 12) radius 18 clockwise from (1.9977, 30) to (17.9977, 20.2462)
  arc A7 centre (-1.9973, 12) radius 18.3 clockwise from (-20.2973, 12) to (-1.9973, 30.3)
  arc A8 centre (1.9977, 12) radius 18.3 clockwise from (1.9977, 30.3) to (20.2977, 12)
  arc A9 centre (-1.9973, 12) radius 20.3224 clockwise from (-22.3197, 12) to (-1.9973, 32.3224)
  arc A10 centre (1.9977, 12) radius 20.3224 clockwise from (1.9977, 32.3224) to (22.32, 12)
  point P20 (-1.9973, 12)
  point P23 (-1.9973, 12)
  point P22 (1.9977, 12)
  point P26 (1.9977, 12)
  point P31 (-1.9973, 12)
  point P34 (1.9977, 12)
  coincident P20 P23
  coincident P22 P26
  tangent A7 L8
  tangent A8 L9
  tangent A8 L10
  coincident P20 P31
  coincident P26 P34
  tangent A9 L11
  tangent A9 L12
  perpendicular L8 L13
  tangent A10 L14
  perpendicular L9 L15
  dimension "d818" distance L7 L10 = 0.3
extrude "Extrude101" new body sketch "Sketch100" profile of A7 A8 L8 L9 L10 A9 A10 L11 L12 L13 L14 L15 against normal blind 227.393
sketch "Sketch101" plane through (22.32, 0, 0) normal (1, 0, 0) x axis (0, 1, 0)
  line L1 (19.0955, -2.8221) -> (19.0955, 12)
  line L2 (246.4885, -2.8221) -> (19.0955, -2.8221)
  line L3 (246.4885, 12) -> (246.4885, -2.8221)
  line L4 (19.0955, 12) -> (246.4885, 12)
  line L5 (258.2426, -22.1021) -> (215, 35)
split "Split38"
remove_body "RemoveBody51"
move_face "MoveFace149"
sketch "Sketch102" plane through (22.32, 0, 0) normal (1, 0, 0) x axis (0, 1, 0)
  line L1 (232.4176, 12) -> (248.6264, -9.4038)
  line L2 (19.0955, 12) -> (232.4176, 12)
  line L3 (19.0955, -9.4038) -> (19.0955, 12)
  line L4 (248.6264, -9.4038) -> (19.0955, -9.4038)
  line L5 (40, 4.4101) -> (19.0955, 4.4101)
  curve K1 (71, -12) -> (40, 4.4101)
  curve K2 (45, 4.4101) -> (35, 4.4101)
  point P6 (19.0955, 4.4101)
  point P7 (40, 4.4101)
  point P11 (35, 4.4101)
  coincident L3 P6
  perpendicular L3 L5
  midpoint P7 K2
  coincident L5 P11
split "Split39"
remove_body "RemoveBody52"
remove_body "RemoveBody53"
offset_faces "OffsetFaces9" distance 1
move_face "MoveFace150"
sketch "Sketch103" plane through (-20.2973, 0, 0) normal (1, 0, 0) x axis (0, 1, 0)
  line L1 (40, 7.4101) -> (19.0955, 7.4101)
  curve K1 (40, 7.4101) -> (71.2934, -9.5817)
  line L2 (248.7611, -9.5817) -> (71.2934, -9.5817)
  line L3 (232.4176, 12) -> (248.7611, -9.5817)
  line L4 (19.0955, 12) -> (232.4176, 12)
  line L5 (19.0955, 7.4101) -> (19.0955, 12)
  line L6 (231.6603, 13) -> (216.2705, 33.3224)
  line L7 (19.0955, 33.3224) -> (216.2705, 33.3224)
  line L8 (19.0955, 33.3224) -> (19.0955, 13)
  line L9 (231.6603, 13) -> (19.0955, 13)
  line L10 (218.5592, 30.3) -> (232.4176, 12)
  line L11 (19.0955, 30.3) -> (218.5592, 30.3)
  line L12 (19.0955, 12) -> (19.0955, 30.3)
  line L13 (232.4176, 12) -> (19.0955, 12)
  line L14 (202.6682, 25) -> (202.6682, 22.3)
  curve K2 (218, 12) -> (202.6682, 22.3)
  line L15 (202.6682, 30.3) -> (202.6682, 22.3)
  line L16 (218.5592, 30.3) -> (202.6682, 30.3)
  line L17 (232.4176, 12) -> (218.5592, 30.3)
  line L18 (232.4176, 12) -> (218, 12)
  point P16 (202.6682, 22.3)
  point P18 (202.6682, 22.3)
  point P20 (218, 12)
  point P21 (202.6682, 30.3)
  point P13 (218.5592, 30.3)
  point P22 (218.5592, 30.3)
  point P23 (218.5592, 30.3)
  point P6 (232.4176, 12)
  point P24 (232.4176, 12)
  point P12 (232.4176, 12)
  point P25 (232.4176, 12)
  coincident P16 P18
  coincident L13 P20
  coincident L11 P21
  perpendicular L11 L15
  coincident P13 P22
  coincident P13 P23
  coincident P6 P24
  coincident P12 P25
extrude "Extrude102" new body sketch "Sketch103" profile of L6 L9 L10 L11 L14 K2 L15 L16 L17 along normal blind 40.595
combine "Combine88"
remove_body "RemoveBody54"
remove_body "RemoveBody55"
move_face "MoveFace151"
offset_faces "OffsetFaces10" distance 0.5
chamfer "Chamfer34" distance 5
chamfer "Chamfer35" distance 4
combine "Combine89"
chamfer "Chamfer36" distance 2
sketch "Sketch104" plane through (0, 0, -9.4038) normal (0, 0, -1) x axis (1, 0, 0)
  line L1 (23.32, -71.2037) -> (20.2977, -71.2037)
  line L2 (20.2977, -248.6264) -> (20.2977, -71.2037)
  line L3 (23.32, -248.6264) -> (20.2977, -248.6264)
  line L4 (23.32, -71.2037) -> (23.32, -248.6264)
  line L5 (20.2977, -248.6264) -> (20.2977, -71.2037)
  curve K1 (14.2527, -245.2882) -> (13.8766, -246.4884)
  line L6 (19.9964, -225.4068) -> (19.9973, -225.4034)
  curve K2 (-13.8766, -246.4884) -> (-14.2527, -245.2882)
  curve K3 (-15.3169, -241.8316) -> (-16.6607, -237.3316)
  line L7 (-19.9973, -225.4034) -> (-19.9964, -225.4068)
  line L8 (-20.2973, -248.7611) -> (-20.2973, -71.2934)
  line L9 (-20.2973, -248.7611) -> (20.2977, -248.6264)
  line L10 (-12.6909, -250.2199) -> (-13.3558, -248.1329)
  line L11 (12.599, -250.5084) -> (13.3558, -248.1329)
  line L12 (13.3558, -248.1329) -> (19.9973, -225.4034)
  line L13 (-13.3558, -248.1329) -> (-19.9973, -225.4034)
  line L14 (11.8807, -254.251) -> (20.2977, -225.4452)
  line L15 (-13.1818, -249.798) -> (-20.2973, -225.4463)
  arc A1 centre (-453.519, -99.3783) radius 490 clockwise from (17.9977, -232.6902) to (17.6992, -233.7413)
  arc A2 centre (-453.519, -99.3783) radius 490 clockwise from (19.9973, -225.4034) to (17.9977, -232.6902)
  arc A3 centre (-453.519, -99.3783) radius 490 clockwise from (15.3169, -241.8316) to (13.3558, -248.1329)
  arc A4 centre (-453.519, -99.3783) radius 490 clockwise from (15.3169, -241.8316) to (14.2527, -245.2882)
  arc A5 centre (453.519, -99.3783) radius 490 clockwise from (-17.6992, -233.7413) to (-17.9977, -232.6902)
  point P7 (20.2977, -248.6264)
  point P29 (20.2977, -248.6264)
  point P28 (-20.2973, -248.7611)
  point P30 (-20.2973, -248.7611)
  point P15 (13.3558, -248.1329)
  point P33 (13.3558, -248.1329)
  point P13 (19.9973, -225.4034)
  point P35 (19.9973, -225.4034)
  point P36 (13.3558, -248.1329)
  point P24 (-19.9973, -225.4034)
  point P37 (-19.9973, -225.4034)
  point P39 (20.2977, -225.4452)
  point P41 (-20.2973, -225.4463)
  coincident P7 P29
  coincident P28 P30
  coincident P15 P33
  tangent A3 L11
  coincident P13 P35
  coincident P15 P36
  coincident P24 P37
  coincident L5 P39
  parallel L12 L14
  coincident L8 P41
  parallel L13 L15
  dimension "d828" distance L13 L15 = 0.3
  dimension "d829" distance L12 L14 = 0.3
extrude "Extrude103" new body sketch "Sketch104" profile of L2 L5 L8 L9 L14 L15 against normal blind 19.404
split "Split40"
remove_body "RemoveBody56"
remove_body "RemoveBody57"
combine "Combine90"
delete_face "DeleteFace92"
delete_face "DeleteFace93"
sketch "Sketch105" plane through (20.2977, 0, 0) normal (-1, 0, 0) x axis (0, -1, 0)
  line L1 (-230.7127, 13.5819) -> (-224.9322, 10)
  line L2 (-230.9136, 13.986) -> (-230.7127, 13.5819)
  line L3 (-233.932, 10.0002) -> (-230.9136, 13.986)
  line L4 (-225.4452, 10.0002) -> (-233.932, 10.0002)
  line L5 (-225.4452, -9.4038) -> (-225.4452, 10.0002)
  line L6 (-71.2037, -9.4038) -> (-225.4452, -9.4038)
  curve K1 (-71.2037, -9.4038) -> (-40, 7.4101)
  line L7 (-19.0955, 7.4101) -> (-40, 7.4101)
  line L8 (-19.0955, 12) -> (-19.0955, 7.4101)
  line L9 (-218, 12) -> (-19.0955, 12)
  line L10 (-219.4472, 10) -> (-218, 12)
  line L11 (-224.9322, 10) -> (-219.4472, 10)
  line L12 (-224.9322, 10) -> (-225.4452, 10.0002)
  point P6 (-225.4452, 10.0002)
  point P14 (-225.4452, 10.0002)
  point P2 (-224.9322, 10)
  point P15 (-224.9322, 10)
  coincident P6 P14
  coincident P2 P15
extrude "Extrude104" new body sketch "Sketch105" profile of L1 L2 L3 L4 L12 along normal blind 11.293
mirror "Mirror28" mirrorStitchTolerance 0.1
combine "Combine91"
move_face "MoveFace152"
fillet "Fillet120" radius 1.7
chamfer "Chamfer37" distance 1
chamfer "Chamfer38" distance 1
fillet "Fillet121" radius 0.5
chamfer "Chamfer39" distance 0.5
split "Split41"
remove_body "RemoveBody58"
mirror "Mirror29" mirrorStitchTolerance 0.1
sketch "Sketch106" plane through (0, 19.0955, 0) normal (0, -1, 0) x axis (1, 0, 0)
  line L1 (-1.9973, 32.3224) -> (1.9973, 32.3224)
  line L2 (-22.3197, 7.4101) -> (-22.3197, 12)
  line L3 (-20.7973, 7.4101) -> (-22.3197, 7.4101)
  line L4 (-20.7973, 12) -> (-20.7973, 7.4101)
  line L5 (1.9973, 30.8) -> (-1.9973, 30.8)
  line L6 (20.7973, 7.4101) -> (20.7973, 12)
  line L7 (22.3197, 7.4101) -> (20.7973, 7.4101)
  line L8 (22.3197, 12) -> (22.3197, 7.4101)
  line L9 (-1.9973, 32.3224) -> (1.9973, 32.3224)
  line L10 (-1.9973, 39.6776) -> (-1.9973, 32.3224)
  line L11 (1.9973, 39.6776) -> (-1.9973, 39.6776)
  line L12 (1.9973, 32.3224) -> (1.9973, 39.6776)
  line L13 (-1.9973, 39.6776) -> (1.9973, 32.3224)
  line L14 (1.9973, 39.6776) -> (-1.9973, 32.3224)
  arc A1 centre (-1.9973, 12) radius 20.3224 clockwise from (-22.3197, 12) to (-1.9973, 32.3224)
  arc A2 centre (-1.9973, 12) radius 18.8 clockwise from (-20.7973, 12) to (-1.9973, 30.8)
  arc A3 centre (1.9973, 12) radius 18.8 clockwise from (1.9973, 30.8) to (20.7973, 12)
  arc A4 centre (1.9973, 12) radius 20.3224 clockwise from (1.9973, 32.3224) to (22.3197, 12)
  point P20 (0, 36)
  point P2 (1.9973, 32.3224)
  point P16 (1.9973, 32.3224)
  horizontal L9
  perpendicular L9 L10
  parallel L9 L11
  parallel L10 L12
  coincident L13 P20
  coincident L14 P20
  coincident P2 P16
extrude "Extrude105" add sketch "Sketch106" profile of L1 L9 L10 L11 L12 blind -19 from offset -7
sketch "Sketch107" plane through (1.9973, 0, 0) normal (1, 0, 0) x axis (0, 1, 0)
  line L1 (45.0955, 33.3224) -> (26.0955, 33.3224)
  line L2 (45.0955, 39.6776) -> (45.0955, 33.3224)
  line L3 (26.0955, 39.6776) -> (45.0955, 39.6776)
  line L4 (26.0955, 33.3224) -> (26.0955, 39.6776)
  line L5 (27.8504, 38.3834) -> (26.0955, 33.3224)
  line L6 (41, 38.3834) -> (27.8504, 38.3834)
  line L7 (45.0955, 33.3224) -> (41, 38.3834)
  point P2 (26.0955, 33.3224)
  point P6 (26.0955, 33.3224)
  point P3 (45.0955, 33.3224)
  point P9 (45.0955, 33.3224)
  coincident P2 P6
  perpendicular L4 L6
  coincident P3 P9
extrude "Extrude106" cut sketch "Sketch107" profile of L2 L3 L4 L5 L6 L7 against normal blind 35
fillet "Fillet122" radius 2.5
move_face "MoveFace153" TranslateX 0 TranslateY 0.5 TranslateZ 0
fillet "Fillet123" radius 0.5
move "Move66" TranslateX 0 TranslateY -3 TranslateZ -1.7
sketch "Sketch108" plane through (-23.3197, 0, 0) normal (-1, 0, 0) x axis (0, -1, 0)
  curve K1 (-71.909, -8.5817) -> (-40, 8.4101)
  line L1 (-20.0955, 8.4101) -> (-40, 8.4101)
  line L2 (-20.0955, 12) -> (-20.0955, 8.4101)
  line L3 (-245.8993, -7.4591) -> (-231.1632, 12)
  line L4 (-71.909, -8.5817) -> (-245.3413, -8.5817)
  line L5 (-135.4511, 5.5097) -> (-99.9434, 5.5097)
  line L6 (-99.9434, 29.488) -> (-135.4511, 29.488)
  line L7 (-135.4511, 29.488) -> (-99.9434, 5.5097)
  line L8 (-99.9434, 29.488) -> (-135.4511, 5.5097)
  arc A1 centre (-245.3413, -7.8817) radius 0.7 clockwise from (-245.3413, -8.5817) to (-245.8993, -7.4591)
  arc A2 centre (-134.1025, 17.4989) radius 12.0648 clockwise from (-135.4511, 5.5097) to (-135.4511, 29.488)
  arc A3 centre (-102.1732, 17.4989) radius 12.1947 clockwise from (-99.9434, 29.488) to (-99.9434, 5.5097)
  point P14 (-117.6973, 17.4989)
  horizontal L5
  parallel L5 L6
  coincident L7 P14
  coincident L8 P14
extrude "Extrude107" new body sketch "Sketch108" profile of L5 L6 A2 A3 along normal blind 20
move "Move67" TranslateX 0 TranslateY 1 TranslateZ 0
move "Move68" TranslateX 10 TranslateY 0 TranslateZ 0
split "Split42"
remove_body "RemoveBody59"
fillet "Fillet124" radius 0.5
move "Move69" TranslateX 0.4 TranslateY 0 TranslateZ 0
combine "Combine92"
sketch "Sketch109" plane through (-23.3197, 0, 0) normal (-1, 0, 0) x axis (0, -1, 0)
  curve K1 (-145.8302, 12) -> (-145.7073, 11.7671)
  line L1 (-231.1632, 12) -> (-145.8302, 12)
  line L2 (-245.8993, -7.4591) -> (-231.1632, 12)
  line L3 (-71.909, -8.5817) -> (-245.3413, -8.5817)
  curve K2 (-71.909, -8.5817) -> (-40, 8.4101)
  line L4 (-20.0955, 8.4101) -> (-40, 8.4101)
  line L5 (-20.0955, 12) -> (-20.0955, 8.4101)
  line L6 (-92.2997, 12) -> (-20.0955, 12)
  curve K3 (-92.4195, 11.7696) -> (-92.2997, 12)
  curve K4 (-100.9444, 5.5198) -> (-92.4195, 11.7696)
  line L7 (-136.4506, 5.5198) -> (-100.9444, 5.5198)
  line L8 (-220, -7) -> (-223, -7)
  line L9 (-209, 23) -> (-220, -7)
  line L10 (-212, 23) -> (-209, 23)
  line L11 (-223, -7) -> (-212, 23)
  arc A1 centre (-245.3413, -7.8817) radius 0.7 clockwise from (-245.3413, -8.5817) to (-245.8993, -7.4591)
  arc A2 centre (-135.1025, 17.4989) radius 12.0547 clockwise from (-136.4506, 5.5198) to (-145.7073, 11.7671)
  horizontal L8
  parallel L1 L10
  parallel L9 L11
extrude "Extrude108" new body sketch "Sketch109" profile of L1 L8 L9 L10 L11 along normal blind 10
move "Move70" TranslateX 4 TranslateY 0 TranslateZ 0
split "Split43"
remove_body "RemoveBody60"
fillet "Fillet125" radius 1
path_pattern "PathPattern2" PathPatternDelta 21.61
mirror "Mirror30" mirrorStitchTolerance 0.1
move "Move71" TranslateX -1 TranslateY 0 TranslateZ 0
move "Move72" TranslateX 1 TranslateY 0 TranslateZ 0
combine "Combine93"
sketch "Sketch110" plane through (0, 6.0841, -36.9971) normal (0, 0.1623, -0.9867) x axis (-1, 0, 0)
  line L1 (8.005, 231.1052) -> (8.005, 222.5007)
  line L2 (-8.005, 231.1052) -> (8.005, 231.1052)
  line L3 (-8.005, 222.5007) -> (-8.005, 231.1052)
  line L4 (8.005, 222.5007) -> (-8.005, 222.5007)
  line L5 (-5.0979, 231.1052) -> (5.0979, 231.1052)
  line L6 (-5.0979, 213.8963) -> (-5.0979, 231.1052)
  line L7 (5.0979, 213.8963) -> (-5.0979, 213.8963)
  line L8 (5.0979, 231.1052) -> (5.0979, 213.8963)
  line L9 (-5.0979, 213.8963) -> (5.0979, 231.1052)
  line L10 (5.0979, 213.8963) -> (-5.0979, 231.1052)
  line L11 (5.0979, 213.8963) -> (-5.0979, 213.8963)
  line L12 (5.0979, 206.3121) -> (5.0979, 213.8963)
  line L13 (-5.0979, 206.3121) -> (5.0979, 206.3121)
  line L14 (-5.0979, 213.8963) -> (-5.0979, 206.3121)
  point P10 (0, 222.5007)
  point P6 (5.0979, 231.1052)
  horizontal L5
  perpendicular L5 L6
  parallel L5 L7
  parallel L6 L8
  coincident L9 P10
  coincident L10 P10
  coincident L2 P6
  midpoint L4 P10
  horizontal L11
  vertical L12
  horizontal L13
  vertical L14
extrude "Extrude109" add sketch "Sketch110" profile of L2 L4 L5 L6 L7 L8 L11 L12 L13 L14 along normal blind 4
move_face "MoveFace154" TranslateX 0 TranslateY 0 TranslateZ 4
move_face "MoveFace155" TranslateX 0 TranslateY 0 TranslateZ 4.054
move_face "MoveFace156" TranslateX -2.907 TranslateY 0 TranslateZ 0
move_face "MoveFace157" TranslateX 2.907 TranslateY 0 TranslateZ 0
sketch "Sketch111" plane through (0, 19.0955, 0) normal (0, -1, 0) x axis (1, 0, 0)
  line L1 (-1.9973, 28) -> (1.9977, 28)
  line L2 (-17.9973, -3.324) -> (-17.9973, 12)
  line L3 (17.9977, -3.324) -> (-17.9973, -3.324)
  line L4 (17.9977, 12) -> (17.9977, -3.324)
  arc A1 centre (1.9977, 12) radius 16 clockwise from (1.9977, 28) to (17.9977, 12)
  arc A2 centre (-1.9973, 12) radius 16 clockwise from (-17.9973, 12) to (-1.9973, 28)
  circle C1 centre (0, 13.7351) radius 13.7351
  circle C2 centre (0, 13.7351) radius 13.7351
  circle C3 centre (0, 13.7351) radius 13.95
  circle C4 centre (0, 13.7351) radius 15.4523
  concentric C2 C3
  concentric C3 C4
  dimension "d904" diameter C3 = 27.9
extrude "Extrude110" new body sketch "Sketch111" profile of A1 L1 A2 C3 C4 along normal blind 5 bodies "Safty Tip"
fillet "Fillet126" radius 0.5
delete_face "DeleteFace94"
sketch "Sketch112" plane through (0, 14.0955, 0) normal (0, -1, 0) x axis (1, 0, 0)
  circle C1 centre (0, 13.7351) radius 13.95
  circle C2 centre (0, 13.7351) radius 15.4523
  circle C3 centre (0, 13.7351) radius 15.4523
  circle C4 centre (0, 13.7351) radius 11.8958
  concentric C1 C3
  concentric C3 C4
extrude "Extrude111" new body sketch "Sketch112" along normal blind 2
combine "Combine94"
fillet "Fillet127" radius 1
fillet "Fillet128" radius 1.5
fillet "Fillet129" radius 0.5
sketch "Sketch113" plane through (0, 59.7708, -219.993) normal (0, 0.2622, -0.965) x axis (-1, 0, 0)
  line L1 (14, 190.2538) -> (14, 159.4538)
  line L2 (-2, 202.2538) -> (2, 202.2538)
  line L3 (-14, 159.4538) -> (-14, 190.2538)
  line L4 (2, 147.4538) -> (-2, 147.4538)
  line L5 (2, 190.2538) -> (-2, 159.4538)
  line L6 (-2, 190.2538) -> (2, 190.2538)
  line L7 (2, 159.4538) -> (-2, 190.2538)
  line L8 (-20, 129.7076) -> (-20, 220)
  line L9 (20, 129.7076) -> (-20, 129.7076)
  line L10 (20, 220) -> (20, 129.7076)
  line L11 (-20, 129.7076) -> (20, 220)
  line L12 (20, 129.7076) -> (-20, 220)
  line L13 (20, 222.6664) -> (20, 220)
  line L14 (-20, 222.6664) -> (20, 222.6664)
  line L15 (-20, 220) -> (-20, 222.6664)
  arc A1 centre (2, 190.2538) radius 12 clockwise from (2, 202.2538) to (14, 190.2538)
  arc A2 centre (-2, 190.2538) radius 12 clockwise from (-14, 190.2538) to (-2, 202.2538)
  arc A3 centre (-2, 159.4538) radius 12 clockwise from (-2, 147.4538) to (-14, 159.4538)
  arc A4 centre (2, 159.4538) radius 12 clockwise from (14, 159.4538) to (2, 147.4538)
  point P11 (-2, 159.4538)
  point P14 (-2, 159.4538)
  point P5 (2, 190.2538)
  point P15 (2, 190.2538)
  point P8 (-2, 190.2538)
  point P16 (-2, 190.2538)
  point P13 (2, 159.4538)
  point P17 (2, 159.4538)
  point P22 (0, 174.8538)
  coincident P11 P14
  coincident P5 P15
  coincident P8 P16
  coincident P13 P17
  parallel L8 L10
  coincident L11 P22
  coincident L12 P22
  midpoint L7 P22
  vertical L13
  horizontal L14
  vertical L15
extrude "Extrude112" new body sketch "Sketch113" profile of L1 A1 L2 A2 L3 A3 L4 A4 L8 L9 L10 L13 L14 L15 against normal blind 12
sketch "Sketch114" plane through (0, 195.1783, 53.0288) normal (0, -0.965, -0.2622) x axis (1, 0, 0)
  line L1 (2, -227.9681) -> (-2, -227.9681)
  line L2 (2, -215.9681) -> (2, -227.9681)
  line L3 (-2, -215.9681) -> (2, -215.9681)
  line L4 (-2, -227.9681) -> (-2, -215.9681)
  curve K1 (2, -219.732) -> (2, -224.2042)
  curve K2 (-2, -224.2042) -> (-2, -219.732)
  circle C1 centre (0, -221.9681) radius 3
  arc A1 centre (0, -221.9681) radius 3 clockwise from (2, -224.2042) to (-2, -224.2042)
  arc A2 centre (0, -221.9681) radius 3 clockwise from (-2, -219.732) to (2, -219.732)
extrude "Extrude113" cut sketch "Sketch114" profile of L2 L4 C1 K1 A1 K2 A2 against normal blind 23
sketch "Sketch115" plane through (0, 142.2954, 38.6608) normal (0, 0.965, 0.2622) x axis (-1, 0, 0)
  line L1 (2, -227.9681) -> (-2, -227.9681)
  line L2 (2, -215.9681) -> (2, -227.9681)
  line L3 (-2, -215.9681) -> (2, -215.9681)
  line L4 (-2, -227.9681) -> (-2, -215.9681)
  curve K1 (2, -219.732) -> (2, -224.2042)
  curve K2 (-2, -224.2042) -> (-2, -219.732)
  circle C1 centre (0, -221.9681) radius 3
  arc A1 centre (0, -221.9681) radius 3 clockwise from (2, -224.2042) to (-2, -224.2042)
  arc A2 centre (0, -221.9681) radius 3 clockwise from (-2, -219.732) to (2, -219.732)
extrude "Extrude114" cut sketch "Sketch115" profile of L2 L4 C1 K1 A1 K2 A2 against normal blind 23
combine "Combine95"
sketch "Sketch116" plane through (-20, 0, 0) normal (-1, 0, 0) x axis (0, -1, 0)
  line L1 (-184.9408, -185.985) -> (-274.6475, -161.6122)
  line L2 (-181.7945, -174.4048) -> (-184.9408, -185.985)
  line L3 (-271.5013, -150.032) -> (-181.7945, -174.4048)
  line L4 (-274.6475, -161.6122) -> (-271.5013, -150.032)
  line L5 (-266.069, -163.943) -> (-275.2574, -157.8352)
  line L6 (-178.3074, -184.2546) -> (-191.3097, -184.2546)
  point P7 (-266.069, -163.943)
  point P8 (-191.3097, -184.2546)
  coincident L1 P7
  coincident L1 P8
  horizontal L6
extrude "Extrude115" cut sketch "Sketch116" profile of L1 L2 L4 L5 L6 against normal blind 85
fillet "Fillet130" radius 15
chamfer "Chamfer40" distance 2
chamfer "Chamfer41" distance 2
fillet "Fillet131" radius 2
fillet "Fillet132" radius 2
fillet "Fillet133" radius 3
fillet "Fillet134" radius 2
fillet "Fillet135" radius 0.5
remove_instance "RemoveInstance1"
remove_instance "RemoveInstance2"
remove_instance "RemoveInstance3"
remove_instance "RemoveInstance4"
remove_instance "RemoveInstance5"
remove_instance "RemoveInstance6"
remove_instance "RemoveInstance7"
remove_instance "RemoveInstance8"
remove_instance "RemoveInstance9"
remove_instance "RemoveInstance10"
remove_instance "RemoveInstance11"
remove_instance "RemoveInstance12"
remove_instance "RemoveInstance13"
remove_instance "RemoveInstance14"
remove_instance "RemoveInstance15"
remove_instance "RemoveInstance16"
remove_instance "RemoveInstance17"
remove_instance "RemoveInstance18"
remove_instance "RemoveInstance19"
remove_instance "RemoveInstance20"
remove_instance "RemoveInstance21"
remove_instance "RemoveInstance22"
remove_instance "RemoveInstance23"
remove_instance "RemoveInstance24"
remove_instance "RemoveInstance25"
remove_instance "RemoveInstance26"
